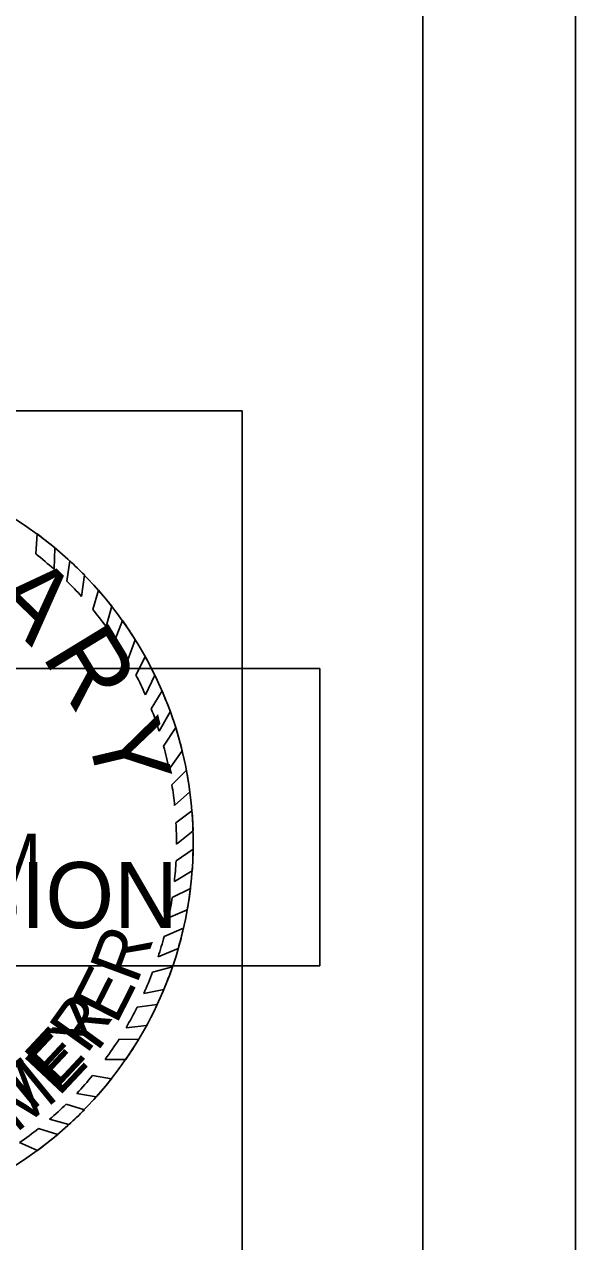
# Model space of a CAD drawing. Extents: x -0.68 to 1.92, y 0 to 0.95.
# Drawn here: x 1.3416 to 1.4167, y 0.0904 to 0.2562 of the extents above; entities that cross this region are included whole.
import ezdxf

# ---------------------------------------------------------------- set-up
doc = ezdxf.new("R2010")
doc.units = 0
for name, color, linetype in [('DSN_DRFT_Guideline-No-Plot', 7, 'Continuous'), ('SHET_Border-Lines', 7, 'Continuous'), ('SHET_Stamp-Prelim', 7, 'Continuous'), ('STAMP_PE_BACKGROUND', 7, 'Continuous'), ('STAMP_PE_FOSTER', 7, 'Continuous'), ('STAMP_PE_SEAL-INFO', 7, 'Continuous'), ('STAMP_PE_TAEGTMEYER', 7, 'Continuous'), ('STAMP_PRELIMINARY', 7, 'Continuous')]:
    doc.layers.add(name, color=color, linetype=linetype)

msp = doc.modelspace()

# ---------------------------------------------------------------- linework, layer by layer
at = {"layer": 'DSN_DRFT_Guideline-No-Plot'}
msp.add_lwpolyline([(0, 0), (1.416666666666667, 0), (1.416666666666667, 0.9166666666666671), (0, 0.9166666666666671)], close=True, dxfattribs=at)
at = {"layer": 'SHET_Border-Lines'}
msp.add_lwpolyline([(0.02083333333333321, 0.02083333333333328), (1.3958333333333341, 0.02083333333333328), (1.3958333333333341, 0.8958333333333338), (0.02083333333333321, 0.8958333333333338)], close=True, dxfattribs=at)
at = {"layer": 'SHET_Stamp-Prelim'}
msp.add_lwpolyline([(1.2006351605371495, 0.127997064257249), (1.3818064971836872, 0.127997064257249), (1.3818064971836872, 0.16844934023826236), (1.2006351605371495, 0.16844934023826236)], close=True, dxfattribs=at)
at = {"layer": 'STAMP_PE_BACKGROUND'}
msp.add_lwpolyline([(1.3712499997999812, 0.20354166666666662), (1.2520833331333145, 0.20354166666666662), (1.2520833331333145, 0.08437499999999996), (1.3712499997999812, 0.08437499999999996)], close=True, dxfattribs=at)
at = {"layer": 'STAMP_PE_SEAL-INFO'}
for p, q in [((1.3431312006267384, 0.18405361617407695), (1.3433223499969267, 0.1867756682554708)), ((1.345625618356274, 0.18197317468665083), (1.3457347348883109, 0.18489311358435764)), ((1.3473716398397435, 0.18034078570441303), (1.3477586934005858, 0.18312570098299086)), ((1.3493777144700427, 0.17825515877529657), (1.349749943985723, 0.18119380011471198)), ((1.3509076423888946, 0.1764874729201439), (1.351669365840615, 0.1791199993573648)), ((1.3527177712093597, 0.174156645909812), (1.3534723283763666, 0.17694663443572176)), ((1.35394615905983, 0.17239577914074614), (1.3549390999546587, 0.1749843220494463)), ((1.3556677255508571, 0.16961743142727), (1.3566877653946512, 0.17236185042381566)), ((1.3567821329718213, 0.1675702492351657), (1.3580476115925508, 0.17005208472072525)), ((1.358071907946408, 0.1648658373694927), (1.3593364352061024, 0.1675737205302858)), ((1.358856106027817, 0.16298184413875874), (1.36033068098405, 0.16540475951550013)), ((1.3599451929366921, 0.15991531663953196), (1.3614566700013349, 0.16256575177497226)), ((1.3605469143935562, 0.1578784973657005), (1.3621878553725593, 0.16040546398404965)), ((1.361289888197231, 0.15475750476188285), (1.3630707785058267, 0.15725240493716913)), ((1.361675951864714, 0.15263366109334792), (1.3636501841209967, 0.15460656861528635)), ((1.362045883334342, 0.1497893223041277), (1.3641275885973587, 0.15166667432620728)), ((1.362226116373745, 0.14745333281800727), (1.3644061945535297, 0.14908358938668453)), ((1.362296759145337, 0.14455951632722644), (1.3645598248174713, 0.14635636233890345)), ((1.3622347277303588, 0.14229607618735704), (1.3645747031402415, 0.14384355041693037)), ((1.3620119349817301, 0.13946818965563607), (1.364437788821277, 0.14090068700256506)), ((1.3617300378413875, 0.13729670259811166), (1.3642048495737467, 0.13852411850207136)), ((1.3612231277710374, 0.13450439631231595), (1.3637650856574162, 0.13559576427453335)), ((1.360621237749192, 0.1319808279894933), (1.3632555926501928, 0.13310648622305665)), ((1.35979979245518, 0.129219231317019), (1.3625386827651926, 0.1303416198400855)), ((1.359047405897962, 0.12709674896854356), (1.3617437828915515, 0.12782925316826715)), ((1.3578509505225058, 0.12422318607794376), (1.3605781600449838, 0.12476258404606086)), ((1.3569513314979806, 0.12234505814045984), (1.3596778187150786, 0.12272524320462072)), ((1.355430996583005, 0.11955873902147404), (1.3582298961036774, 0.11986276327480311)), ((1.3544708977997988, 0.11799213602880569), (1.3571381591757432, 0.11795683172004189)), ((1.3525738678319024, 0.1152306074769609), (1.3553925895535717, 0.11524679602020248)), ((1.350853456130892, 0.11303031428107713), (1.353432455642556, 0.11258595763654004)), ((1.3487131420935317, 0.11061010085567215), (1.3513780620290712, 0.1101337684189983)), ((1.347289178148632, 0.10916184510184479), (1.3497523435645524, 0.10839198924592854)), ((1.345021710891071, 0.10708080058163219), (1.3476546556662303, 0.10636220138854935)), ((1.3435092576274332, 0.10582761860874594), (1.3461231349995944, 0.10501531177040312)), ((1.3409364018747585, 0.10391206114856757), (1.3433867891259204, 0.10285504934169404))]:
    msp.add_line(p, q, dxfattribs=at)
for radius, start, end in [(0.05208333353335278, 50.34919923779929, 53.715927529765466), (0.04979730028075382, 48.301629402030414, 52.0395271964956), (0.05208333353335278, 44.34049610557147, 47.392920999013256), (0.04979730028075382, 42.221157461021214, 45.55119386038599), (0.05208333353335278, 38.12472275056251, 41.2315730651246), (0.04979730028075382, 36.135025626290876, 39.53106373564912), (0.05208333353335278, 31.96138013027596, 35.42937309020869), (0.04979730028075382, 29.903213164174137, 33.66454441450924), (0.05208333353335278, 25.939091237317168, 29.012473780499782), (0.04979730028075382, 23.77322286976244, 27.221139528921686), (0.05208333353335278, 19.953806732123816, 23.314091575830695), (0.04979730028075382, 17.68022309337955, 21.42508660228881), (0.05208333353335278, 13.842052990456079, 17.444684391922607), (0.04979730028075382, 11.544448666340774, 15.236388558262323), (0.05208333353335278, 7.585188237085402, 10.862114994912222), (0.04979730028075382, 5.7598993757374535, 9.06055796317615), (0.05208333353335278, 1.7215475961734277, 4.7268136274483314), (0.04979730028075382, 359.7328912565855, 3.0639197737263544), (0.05208333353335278, 355.71562332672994, 358.956939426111), (0.04979730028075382, 353.86318650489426, 357.12741991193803), (0.05208333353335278, 349.83046937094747, 353.08845194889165), (0.04979730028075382, 348.07782395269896, 351.34354893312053), (0.05208333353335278, 343.8924710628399, 347.03501976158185), (0.04979730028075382, 341.7769864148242, 345.0924752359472), (0.05208333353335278, 337.3836727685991, 340.99332282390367), (0.04979730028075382, 335.60379596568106, 339.1857838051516), (0.05208333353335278, 331.4037138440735, 334.933154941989), (0.04979730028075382, 329.55488416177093, 333.20757358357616), (0.04979730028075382, 323.58513069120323, 327.44068976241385), (0.05208333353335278, 325.4405170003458, 328.9872482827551), (0.04979730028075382, 316.6530849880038, 320.3710862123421), (0.05208333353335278, 318.2845512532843, 321.8042854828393), (0.04979730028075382, 310.7743619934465, 314.31605044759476), (0.05208333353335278, 312.45177291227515, 315.66328088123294), (0.04979730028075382, 304.8229923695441, 308.51427595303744), (0.05208333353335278, 306.37206251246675, 310.20798964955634)]:
    msp.add_arc((1.3125000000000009, 0.14479166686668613), radius, start, end, dxfattribs=at)
at = {"layer": 'STAMP_PRELIMINARY'}
msp.add_circle((1.3125000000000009, 0.14479166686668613), 0.05208333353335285, dxfattribs=at)

# ---------------------------------------------------------------- texts
at = {"layer": 'SHET_Stamp-Prelim'}
msp.add_text('SUBJECT TO REVISION', height=0.009, dxfattribs=at).set_placement((1.2267484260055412, 0.13311013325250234))
at = {"layer": 'STAMP_PE_FOSTER'}
for s, height, rotation, p in [('R', 0.006704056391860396, 54.50309997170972, (1.350066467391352, 0.11580297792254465)), ('E', 0.006704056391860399, 46.96130660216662, (1.3460238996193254, 0.11121650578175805)), ('T', 0.006704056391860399, 39.41937898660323, (1.3412284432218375, 0.1070258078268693))]:
    msp.add_text(s, height=height, rotation=rotation, dxfattribs=at).set_placement(p)
at = {"layer": 'STAMP_PE_TAEGTMEYER'}
for s, height, rotation, p in [('R', 0.006983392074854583, 69.57000985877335, (1.3568870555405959, 0.12531919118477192)), ('E', 0.00698339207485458, 63.09839547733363, (1.3541015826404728, 0.11983535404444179)), ('Y', 0.006983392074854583, 53.99864225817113, (1.3503639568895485, 0.11458068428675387)), ('E', 0.006983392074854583, 46.80937910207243, (1.3462349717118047, 0.11002725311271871)), ('M', 0.00698339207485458, 39.30004668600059, (1.3404223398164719, 0.1051158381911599))]:
    msp.add_text(s, height=height, rotation=rotation, dxfattribs=at).set_placement(p)
at = {"layer": 'STAMP_PRELIMINARY'}
for s, height, rotation, p in [('A', 0.010056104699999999, 315.65789090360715, (1.3362148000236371, 0.17755060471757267)), ('R', 0.010056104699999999, 301.38306156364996, (1.343856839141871, 0.17020900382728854)), ('Y', 0.010056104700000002, 283.25926303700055, (1.3499420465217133, 0.16022803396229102))]:
    msp.add_text(s, height=height, rotation=rotation, dxfattribs=at).set_placement(p)
msp.add_text('PICKERING FIRM', height=0.006983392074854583, dxfattribs=at).set_placement((1.2670979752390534, 0.1389994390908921))

doc.saveas('drawing.dxf')
